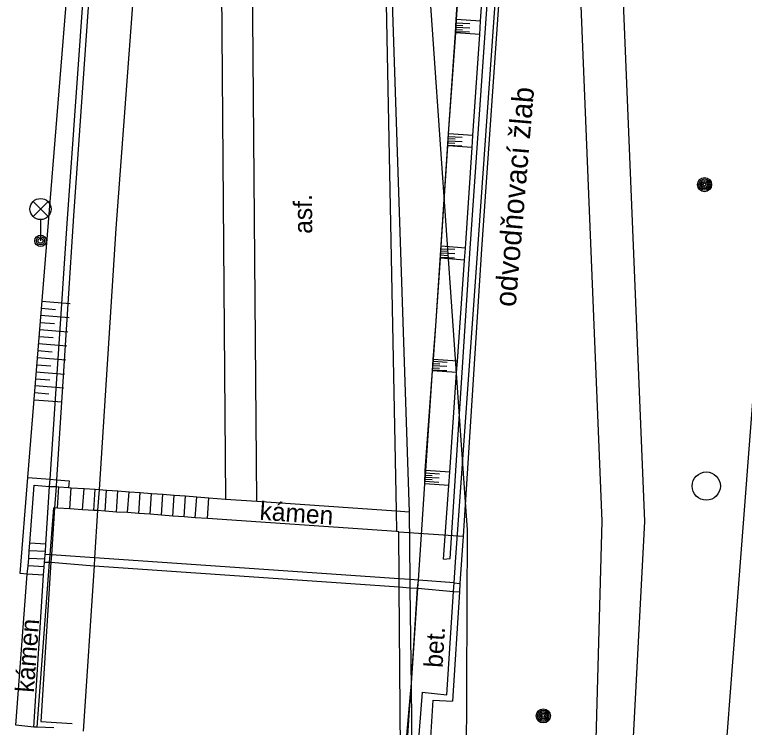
# Model space of a CAD drawing. Extents: x -599951 to -598963, y -1164095 to -1162939.
# Drawn here: x -599187.6 to -599161.76, y -1163812.19 to -1163786.94 of the extents above; entities that cross this region are included whole.
import ezdxf

# ---------------------------------------------------------------- set-up
doc = ezdxf.new("R2010")
doc.units = 0
for name, color, linetype in [('Level 10', 7, 'Continuous'), ('Level 11', 7, 'Continuous'), ('Level 13', 7, 'Continuous'), ('Level 15', 7, 'Continuous'), ('Level 25', 7, 'Continuous'), ('Level 27', 7, 'Continuous'), ('Level 33', 7, 'Continuous'), ('Level 40', 7, 'Continuous'), ('Level 41', 7, 'Continuous'), ('Level 9', 7, 'Continuous')]:
    doc.layers.add(name, color=color, linetype=linetype)

msp = doc.modelspace()

# ---------------------------------------------------------------- linework, layer by layer
at = {"layer": 'Level 10'}
for points in [[(-599162.85, -1163820.04), (-599162.62, -1163815.71), (-599158.85, -1163766.66), (-599157.06, -1163745.81), (-599155.93, -1163733.73), (-599156.18, -1163710.45), (-599156.98, -1163691.85), (-599157.68, -1163676.6)], [(-599171.97, -1163787.11), (-599171.73, -1163783.6)], [(-599171.99, -1163787.58), (-599171.97, -1163787.11)], [(-599172.24, -1163791.16), (-599171.99, -1163787.58)], [(-599172.26, -1163791.58), (-599172.24, -1163791.16)], [(-599172.5, -1163795.14), (-599172.26, -1163791.58)], [(-599172.52, -1163795.57), (-599172.5, -1163795.14)], [(-599172.69, -1163797.96), (-599172.52, -1163795.57)], [(-599172.78, -1163799.15), (-599172.69, -1163797.96)], [(-599172.8, -1163799.56), (-599172.78, -1163799.15)], [(-599173.06, -1163803.09), (-599172.8, -1163799.56)], [(-599173.08, -1163803.56), (-599173.06, -1163803.09)], [(-599173.3, -1163806.97), (-599173.08, -1163803.56)], [(-599173.33, -1163807.26), (-599173.3, -1163806.97)], [(-599173.56, -1163810.78), (-599173.33, -1163807.26)], [(-599173.71, -1163813.01), (-599173.57, -1163810.87)], [(-599173.57, -1163810.87), (-599173.56, -1163810.78)]]:
    msp.add_lwpolyline(points, dxfattribs=at)
at = {"layer": 'Level 11'}
for points in [[(-599172.41, -1163806.23), (-599172.18, -1163806.21), (-599171.47, -1163795.22), (-599170.36, -1163779.27), (-599168.86, -1163759.58)], [(-599166.11, -1163820.59), (-599165.29, -1163804.89), (-599166.1, -1163785.06), (-599167.63, -1163770.52), (-599168.62, -1163761.72)], [(-599187.13, -1163803.34), (-599185.61, -1163784.52), (-599184.5, -1163762.51), (-599183.39, -1163762.56)], [(-599186.34, -1163803.4), (-599185.74, -1163794.34), (-599184.56, -1163777.73), (-599183.39, -1163762.56)], [(-599179.94, -1163762.72), (-599180.29, -1163784.57), (-599180.13, -1163804.1)], [(-599169.96, -1163779.3), (-599171.07, -1163795.25), (-599171.72, -1163805.42), (-599171.83, -1163807.09)], [(-599171.1, -1163787.17), (-599170.86, -1163783.66)], [(-599179.02, -1163804.18), (-599179.19, -1163784.15)], [(-599174.47, -1163785.35), (-599174.09, -1163804.52)], [(-599174.27, -1163785.42), (-599173.63, -1163804.55)], [(-599171.95, -1163787.11), (-599171.97, -1163787.11)], [(-599171.1, -1163787.17), (-599171.95, -1163787.11)], [(-599171.13, -1163787.64), (-599171.1, -1163787.17)], [(-599171.98, -1163787.58), (-599171.99, -1163787.58)], [(-599171.13, -1163787.64), (-599171.98, -1163787.58)], [(-599171.37, -1163791.22), (-599171.13, -1163787.64)], [(-599171.37, -1163791.22), (-599172.24, -1163791.16)], [(-599171.4, -1163791.64), (-599171.37, -1163791.22)], [(-599171.4, -1163791.64), (-599172.26, -1163791.58)], [(-599171.64, -1163795.21), (-599171.4, -1163791.64)], [(-599171.64, -1163795.21), (-599172.5, -1163795.14)], [(-599171.67, -1163795.63), (-599171.64, -1163795.21)], [(-599171.67, -1163795.63), (-599172.52, -1163795.57)], [(-599171.92, -1163799.21), (-599171.67, -1163795.63)], [(-599172.77, -1163799.15), (-599172.78, -1163799.15)], [(-599171.92, -1163799.21), (-599172.77, -1163799.15)], [(-599171.95, -1163799.62), (-599171.92, -1163799.21)], [(-599171.95, -1163799.62), (-599172.8, -1163799.56)], [(-599172.19, -1163803.15), (-599171.95, -1163799.62)], [(-599173.04, -1163803.09), (-599173.06, -1163803.09)], [(-599172.19, -1163803.15), (-599173.04, -1163803.09)], [(-599172.23, -1163803.62), (-599172.19, -1163803.15)], [(-599187.15, -1163806.76), (-599187.4, -1163806.74), (-599187.13, -1163803.34)], [(-599187.13, -1163803.34), (-599186.34, -1163803.4)], [(-599186.36, -1163803.65), (-599186.34, -1163803.4)], [(-599186.34, -1163803.4), (-599186.12, -1163803.42)], [(-599186.12, -1163803.42), (-599185.67, -1163803.45), (-599185.69, -1163803.69)], [(-599187.06, -1163805.66), (-599186.9, -1163803.61), (-599186.36, -1163803.65)], [(-599186.49, -1163805.7), (-599186.36, -1163803.65)], [(-599186.36, -1163803.65), (-599186.13, -1163803.66)], [(-599186.13, -1163803.66), (-599186.03, -1163803.67)], [(-599186.08, -1163804.42), (-599186.03, -1163803.67)], [(-599186.03, -1163803.67), (-599185.69, -1163803.69)], [(-599185.69, -1163803.69), (-599185.59, -1163803.7)], [(-599185.64, -1163804.45), (-599185.59, -1163803.7)], [(-599185.59, -1163803.7), (-599185.14, -1163803.73)], [(-599185.19, -1163804.48), (-599185.14, -1163803.73)], [(-599185.14, -1163803.73), (-599184.74, -1163803.75)], [(-599184.79, -1163804.5), (-599184.74, -1163803.75)], [(-599184.74, -1163803.75), (-599184.61, -1163803.76)], [(-599184.61, -1163803.76), (-599184.34, -1163803.78)], [(-599184.39, -1163804.53), (-599184.34, -1163803.78)], [(-599184.34, -1163803.78), (-599183.94, -1163803.81)], [(-599173.07, -1163803.56), (-599173.08, -1163803.56)], [(-599172.23, -1163803.62), (-599173.07, -1163803.56)], [(-599172.41, -1163806.23), (-599172.23, -1163803.62)], [(-599183.99, -1163804.56), (-599183.94, -1163803.81)], [(-599183.94, -1163803.81), (-599183.54, -1163803.84)], [(-599183.6, -1163804.58), (-599183.54, -1163803.84)], [(-599183.54, -1163803.84), (-599183.15, -1163803.87)], [(-599183.2, -1163804.61), (-599183.15, -1163803.87)], [(-599183.15, -1163803.87), (-599182.75, -1163803.9)], [(-599182.8, -1163804.64), (-599182.75, -1163803.9)], [(-599182.75, -1163803.9), (-599182.35, -1163803.93)], [(-599182.4, -1163804.67), (-599182.35, -1163803.93)], [(-599182.35, -1163803.93), (-599181.95, -1163803.96)], [(-599182, -1163804.7), (-599181.95, -1163803.96)], [(-599181.95, -1163803.96), (-599181.55, -1163803.99)], [(-599181.6, -1163804.73), (-599181.55, -1163803.99)], [(-599181.55, -1163803.99), (-599181.15, -1163804.02)], [(-599181.2, -1163804.76), (-599181.15, -1163804.02)], [(-599181.15, -1163804.02), (-599180.72, -1163804.06)], [(-599180.77, -1163804.79), (-599180.72, -1163804.06)], [(-599180.72, -1163804.06), (-599180.13, -1163804.1)], [(-599180.13, -1163804.1), (-599179.02, -1163804.18)], [(-599179.02, -1163804.18), (-599174.09, -1163804.52)], [(-599186.34, -1163806.07), (-599186.21, -1163804.41)], [(-599186.18, -1163804.41), (-599186.21, -1163804.41)], [(-599186.08, -1163804.42), (-599186.18, -1163804.41)], [(-599185.64, -1163804.45), (-599186.08, -1163804.42)], [(-599185.19, -1163804.48), (-599185.64, -1163804.45)], [(-599184.79, -1163804.5), (-599185.19, -1163804.48)], [(-599184.66, -1163804.51), (-599184.79, -1163804.5)], [(-599184.39, -1163804.53), (-599184.66, -1163804.51)], [(-599183.99, -1163804.56), (-599184.39, -1163804.53)], [(-599174.09, -1163804.52), (-599174.08, -1163805.25)], [(-599174.09, -1163804.52), (-599173.63, -1163804.55)], [(-599173.63, -1163804.55), (-599173.6, -1163806.95)], [(-599183.6, -1163804.58), (-599183.99, -1163804.56)], [(-599183.2, -1163804.61), (-599183.6, -1163804.58)], [(-599182.8, -1163804.64), (-599183.2, -1163804.61)], [(-599182.4, -1163804.67), (-599182.8, -1163804.64)], [(-599182, -1163804.7), (-599182.4, -1163804.67)], [(-599181.6, -1163804.73), (-599182, -1163804.7)], [(-599181.2, -1163804.76), (-599181.6, -1163804.73)], [(-599180.77, -1163804.79), (-599181.2, -1163804.76)], [(-599174.08, -1163805.25), (-599180.77, -1163804.79)], [(-599173.98, -1163806.92), (-599173.99, -1163805.26), (-599174.08, -1163805.25)], [(-599173.99, -1163805.26), (-599171.72, -1163805.42)], [(-599187.08, -1163805.93), (-599187.06, -1163805.66)], [(-599186.49, -1163805.7), (-599187.06, -1163805.66)], [(-599186.51, -1163805.96), (-599186.49, -1163805.7)], [(-599187.1, -1163806.2), (-599187.08, -1163805.93)], [(-599186.51, -1163805.96), (-599187.08, -1163805.93)], [(-599186.53, -1163806.23), (-599186.52, -1163806.06)], [(-599186.52, -1163806.06), (-599186.51, -1163805.96)], [(-599186.34, -1163806.07), (-599186.52, -1163806.06)], [(-599186.36, -1163806.34), (-599186.34, -1163806.07)], [(-599186.29, -1163806.07), (-599186.34, -1163806.07)], [(-599184.77, -1163806.18), (-599186.29, -1163806.07)], [(-599187.12, -1163806.46), (-599187.1, -1163806.2)], [(-599186.53, -1163806.23), (-599187.1, -1163806.2)], [(-599186.8, -1163812.18), (-599186.36, -1163806.34)], [(-599186.55, -1163806.5), (-599186.54, -1163806.33)], [(-599186.54, -1163806.33), (-599186.53, -1163806.23)], [(-599186.54, -1163806.33), (-599186.36, -1163806.34)], [(-599186.36, -1163806.34), (-599186.31, -1163806.34)], [(-599186.31, -1163806.34), (-599184.78, -1163806.47)], [(-599173.98, -1163806.92), (-599184.77, -1163806.18)], [(-599187.15, -1163806.76), (-599187.12, -1163806.46)], [(-599186.55, -1163806.5), (-599187.12, -1163806.46)], [(-599186.57, -1163806.8), (-599186.55, -1163806.5)], [(-599184.78, -1163806.47), (-599173.98, -1163807.21)], [(-599186.92, -1163812.18), (-599187.55, -1163812.11), (-599187.15, -1163806.76)], [(-599186.57, -1163806.8), (-599187.15, -1163806.76)], [(-599186.92, -1163812.18), (-599186.57, -1163806.8)], [(-599173.98, -1163807.21), (-599173.98, -1163806.92)], [(-599173.6, -1163806.95), (-599173.98, -1163806.92)], [(-599173.3, -1163806.97), (-599173.6, -1163806.95)], [(-599173.6, -1163806.95), (-599173.6, -1163807.24)], [(-599172.04, -1163807.07), (-599173.3, -1163806.97)], [(-599172.04, -1163807.07), (-599171.83, -1163807.09)], [(-599171.83, -1163807.09), (-599171.85, -1163807.39)], [(-599173.98, -1163807.21), (-599173.6, -1163807.24)], [(-599173.93, -1163813.01), (-599173.98, -1163807.21)], [(-599173.6, -1163807.24), (-599173.33, -1163807.26)], [(-599173.6, -1163807.24), (-599173.56, -1163810.78)], [(-599173.33, -1163807.26), (-599173.32, -1163807.26)], [(-599173.32, -1163807.26), (-599172.06, -1163807.37)], [(-599171.85, -1163807.39), (-599172.1, -1163811.26)], [(-599172.06, -1163807.37), (-599171.85, -1163807.39)], [(-599173.56, -1163810.8), (-599173.54, -1163813.01), (-599173.71, -1163813.01)], [(-599173.56, -1163810.78), (-599173.56, -1163810.8)], [(-599173.71, -1163813.02), (-599172.9, -1163813.11), (-599172.78, -1163811.22), (-599172.1, -1163811.26)], [(-599186.8, -1163812.18), (-599186.92, -1163812.18)], [(-599186.21, -1163812.2), (-599186.8, -1163812.18)]]:
    msp.add_lwpolyline(points, dxfattribs=at)
at = {"layer": 'Level 13'}
for points in [[(-599179.8, -1163722.27), (-599178.84, -1163730.55), (-599174.48, -1163771.17), (-599172.99, -1163784.92), (-599171.65, -1163804.21)], [(-599167.24, -1163821.2), (-599166.79, -1163804.88), (-599167.6, -1163785.17), (-599169.23, -1163769.66)], [(-599167.24, -1163821.2), (-599166.79, -1163804.88), (-599167.6, -1163785.17), (-599169.23, -1163769.66)], [(-599171.65, -1163804.21), (-599171.58, -1163805.18), (-599171.65, -1163821.76)]]:
    msp.add_lwpolyline(points, dxfattribs=at)
at = {"layer": 'Level 15'}
for points in [[(-599171.98, -1163787.23), (-599171.48, -1163787.25)], [(-599171.99, -1163787.46), (-599171.74, -1163787.47)], [(-599171.98, -1163787.31), (-599171.73, -1163787.32)], [(-599171.98, -1163787.38), (-599171.48, -1163787.4)], [(-599171.99, -1163787.53), (-599171.49, -1163787.55)], [(-599172.25, -1163791.26), (-599171.75, -1163791.28)], [(-599172.25, -1163791.33), (-599172, -1163791.34)], [(-599172.26, -1163791.48), (-599172.01, -1163791.49)], [(-599172.26, -1163791.56), (-599171.76, -1163791.58)], [(-599172.25, -1163791.41), (-599171.75, -1163791.43)], [(-599172.5, -1163795.23), (-599172.01, -1163795.25)], [(-599172.52, -1163795.45), (-599172.27, -1163795.47)], [(-599172.51, -1163795.3), (-599172.26, -1163795.32)], [(-599172.51, -1163795.38), (-599172.01, -1163795.4)], [(-599172.52, -1163795.53), (-599172.02, -1163795.55)], [(-599186.63, -1163797.09), (-599185.63, -1163797.17)], [(-599186.65, -1163797.34), (-599186.15, -1163797.38)], [(-599186.69, -1163797.84), (-599186.19, -1163797.88)], [(-599186.67, -1163797.59), (-599185.67, -1163797.67)], [(-599186.71, -1163798.09), (-599185.71, -1163798.17)], [(-599186.73, -1163798.34), (-599186.23, -1163798.38)], [(-599186.75, -1163798.59), (-599185.75, -1163798.67)], [(-599186.77, -1163798.84), (-599186.27, -1163798.88)], [(-599186.79, -1163799.09), (-599185.79, -1163799.17)], [(-599186.81, -1163799.34), (-599186.31, -1163799.38)], [(-599172.79, -1163799.3), (-599172.54, -1163799.31)], [(-599172.79, -1163799.37), (-599172.29, -1163799.39)], [(-599172.78, -1163799.22), (-599172.28, -1163799.25)], [(-599186.83, -1163799.59), (-599185.83, -1163799.67)], [(-599172.8, -1163799.52), (-599172.3, -1163799.54)], [(-599172.79, -1163799.45), (-599172.55, -1163799.46)], [(-599186.85, -1163799.84), (-599186.35, -1163799.88)], [(-599186.87, -1163800.08), (-599185.87, -1163800.16)], [(-599186.89, -1163800.33), (-599186.39, -1163800.37)], [(-599186.91, -1163800.58), (-599185.91, -1163800.66)], [(-599173.07, -1163803.25), (-599172.82, -1163803.26)], [(-599173.06, -1163803.17), (-599172.56, -1163803.2)], [(-599173.08, -1163803.47), (-599172.58, -1163803.5)], [(-599173.07, -1163803.32), (-599172.57, -1163803.35)], [(-599173.07, -1163803.4), (-599172.82, -1163803.41)]]:
    msp.add_lwpolyline(points, dxfattribs=at)
at = {"layer": 'Level 25'}
for centre, radius in [((-599163.17, -1163792.96), 0.25), ((-599163.17, -1163792.96), 0.2), ((-599163.17, -1163792.96), 0.15), ((-599163.17, -1163792.96), 0.1), ((-599163.17, -1163792.96), 0.05), ((-599168.88, -1163811.78), 0.25), ((-599168.88, -1163811.78), 0.2), ((-599168.88, -1163811.78), 0.15), ((-599168.88, -1163811.78), 0.1), ((-599168.88, -1163811.78), 0.05)]:
    msp.add_circle(centre, radius, dxfattribs=at)
at = {"layer": 'Level 27'}
msp.add_circle((-599163.11, -1163803.64), 0.5, dxfattribs=at)
at = {"layer": 'Level 33'}
for p, q in [((-599186.945, -1163794.09), (-599186.415, -1163793.56)), ((-599186.945, -1163793.56), (-599186.415, -1163794.09)), ((-599186.68, -1163794.2), (-599186.68, -1163794.95))]:
    msp.add_line(p, q, dxfattribs=at)
for centre, radius in [((-599186.68, -1163793.825), 0.375), ((-599186.68, -1163794.95), 0.2), ((-599186.68, -1163794.95), 0.145), ((-599186.68, -1163794.95), 0.0876)]:
    msp.add_circle(centre, radius, dxfattribs=at)
at = {"layer": 'Level 9'}
for points in [[(-599172.04, -1163807.07), (-599171.99, -1163806.34), (-599171.2, -1163795.24), (-599170.08, -1163779.34), (-599168.69, -1163761.08)], [(-599183.19, -1163762.57), (-599184.37, -1163777.76), (-599185.51, -1163794.06), (-599186.12, -1163803.42)], [(-599181.62, -1163762.64), (-599182.73, -1163777.25), (-599184.01, -1163794.51), (-599184.61, -1163803.76)], [(-599171.95, -1163787.11), (-599171.7, -1163783.6)], [(-599171.98, -1163787.58), (-599171.95, -1163787.11)], [(-599172.24, -1163791.16), (-599171.98, -1163787.58)], [(-599172.69, -1163797.96), (-599172.24, -1163791.16)], [(-599172.77, -1163799.15), (-599172.69, -1163797.96)], [(-599172.8, -1163799.56), (-599172.77, -1163799.15)], [(-599173.04, -1163803.09), (-599172.8, -1163799.56)], [(-599173.07, -1163803.56), (-599173.04, -1163803.09)], [(-599186.12, -1163803.42), (-599186.13, -1163803.66)], [(-599186.13, -1163803.66), (-599186.18, -1163804.41)], [(-599184.61, -1163803.76), (-599184.66, -1163804.51)], [(-599173.3, -1163806.97), (-599173.07, -1163803.56)], [(-599186.18, -1163804.41), (-599186.29, -1163806.07)], [(-599184.66, -1163804.51), (-599184.77, -1163806.18)], [(-599186.29, -1163806.07), (-599186.31, -1163806.34)], [(-599186.31, -1163806.34), (-599186.67, -1163811.98), (-599185.56, -1163812.05)], [(-599184.77, -1163806.18), (-599184.78, -1163806.47)], [(-599184.78, -1163806.47), (-599185.17, -1163812.32)], [(-599173.32, -1163807.26), (-599173.3, -1163806.97)], [(-599172.06, -1163807.37), (-599172.04, -1163807.07)], [(-599173.56, -1163810.8), (-599173.32, -1163807.26)], [(-599173.17, -1163810.94), (-599172.29, -1163811.04), (-599172.06, -1163807.37)], [(-599173.76, -1163813.01), (-599173.57, -1163810.87)], [(-599173.57, -1163810.87), (-599173.56, -1163810.8)], [(-599173.17, -1163810.94), (-599173.33, -1163813.06)]]:
    msp.add_lwpolyline(points, dxfattribs=at)

# ---------------------------------------------------------------- texts
at = {"layer": 'Level 40'}
for s, rotation, p in [('asf.', 90.49, (-599177.06, -1163794.7)), ('kámen', 356.05, (-599178.94, -1163804.83)), ('kámen', 85.71, (-599186.92, -1163810.97)), ('bet.', 86.32, (-599172.45, -1163810.09))]:
    msp.add_text(s, height=0.65, rotation=rotation, dxfattribs=at).set_placement(p)
at = {"layer": 'Level 41'}
msp.add_text('odvodňovací žlab', height=0.75, rotation=85.16, dxfattribs=at).set_placement((-599169.86, -1163797.31))

doc.saveas('drawing.dxf')
